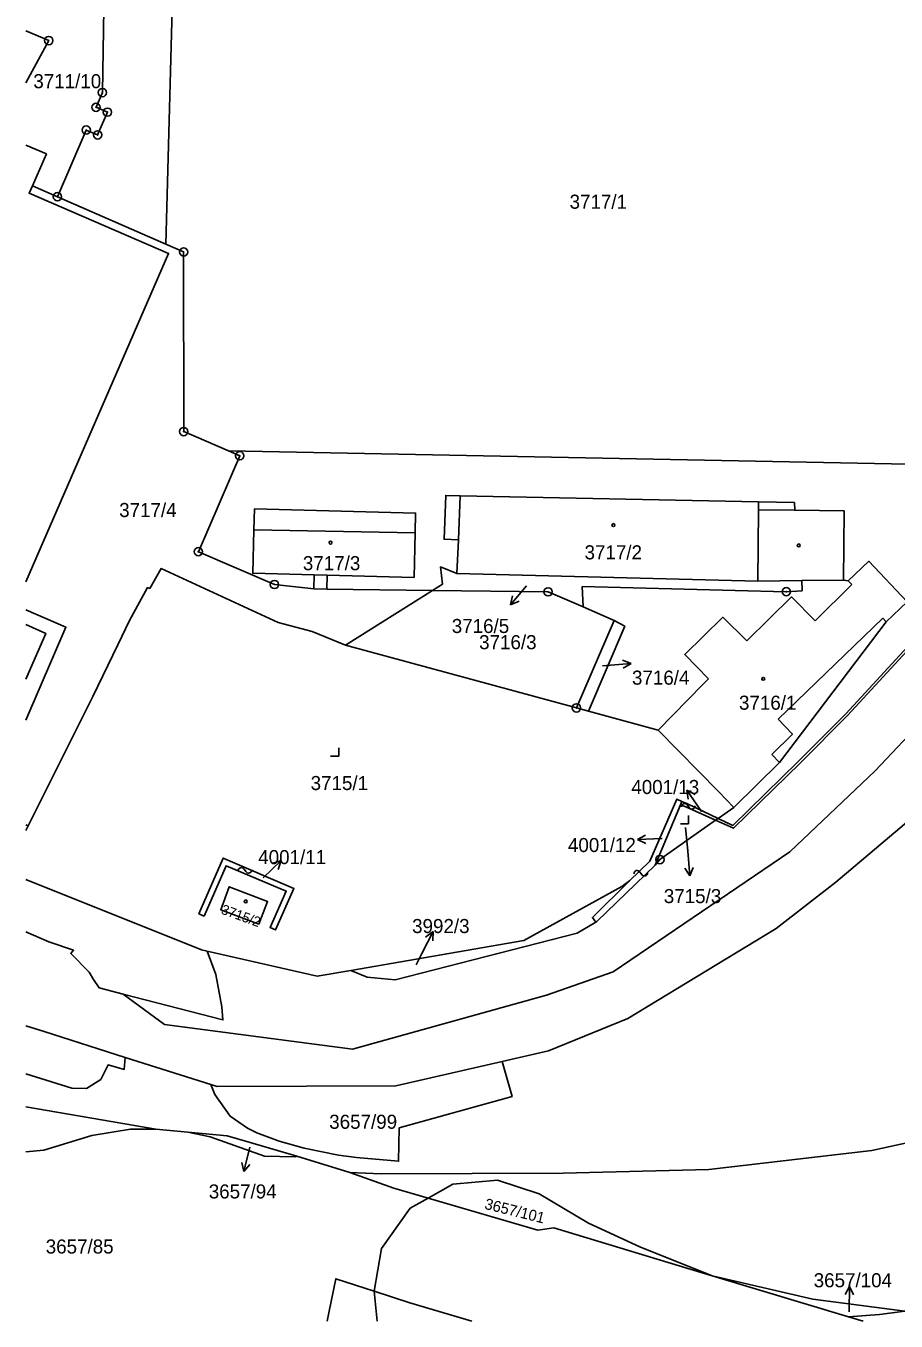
# Model space of a CAD drawing. Extents: x -747779 to -747197, y -965543 to -964919.
# Drawn here: x -747775.5 to -747670.2, y -965537.7 to -965381 of the extents above; entities that cross this region are included whole.
import ezdxf

# ---------------------------------------------------------------- set-up
doc = ezdxf.new("R2010")
doc.units = 0
for name, color, linetype in [('Hranice parcel', 7, 'Continuous'), ('Parcelní čísla', 7, 'Continuous'), ('Pop  PČ popisy', 7, 'Continuous'), ('Vnitřní kresba', 7, 'Continuous'), ('Značky bodu BP', 7, 'Continuous'), ('Značky budov', 7, 'Continuous'), ('Značky kultur', 7, 'Continuous')]:
    doc.layers.add(name, color=color, linetype=linetype)

msp = doc.modelspace()

# ---------------------------------------------------------------- linework, layer by layer
at = {"layer": 'Hranice parcel'}
for p, q in [((-747771.71, -965401.67), (-747774.74, -965400.35)), ((-747740.69, -965449.11), (-747739.11, -965449.15)), ((-747739.11, -965449.15), (-747726.31, -965449.3)), ((-747726.31, -965449.3), (-747736.84, -965455.93)), ((-747681.62, -965448.1), (-747676.6, -965448.05)), ((-747708.09, -965451.3), (-747704.33, -965452.92)), ((-747708.9, -965463.51), (-747704.33, -965452.92)), ((-747708.9, -965463.51), (-747736.84, -965455.93)), ((-747707.46, -965463.9), (-747708.9, -965463.51)), ((-747696.3, -965475.23), (-747699.39, -965482.54)), ((-747696.13, -965474.83), (-747696.3, -965475.23)), ((-747691.74, -965476.88), (-747689.84, -965475.54)), ((-747692.06, -965477.11), (-747691.74, -965476.88)), ((-747775.25, -965477.78), (-747775.53, -965477.67)), ((-747775.53, -965478.34), (-747775.25, -965477.78)), ((-747763.53, -965505.79), (-747753.16, -965509.09)), ((-747755.94, -965514.84), (-747759.81, -965514.49)), ((-747736.34, -965519.7), (-747742.72, -965517.76)), ((-747675.99, -965537.16), (-747692.46, -965532.2))]:
    msp.add_line(p, q, dxfattribs=at)
for points in [[(-747766.44, -965371.1), (-747765.97, -965371.3), (-747766.27, -965389.07), (-747767.04, -965390.85), (-747765.66, -965391.44), (-747766.85, -965394.19), (-747768.23, -965393.6), (-747771.71, -965401.67)], [(-747775.53, -965387.9), (-747772.76, -965382.78), (-747775.53, -965381.59)], [(-747774.74, -965400.35), (-747773.05, -965396.49), (-747775.53, -965395.44)], [(-747775.53, -965448.26), (-747758.26, -965408.52), (-747775.14, -965401.25), (-747774.74, -965400.35)], [(-747771.71, -965401.67), (-747758.58, -965407.41), (-747756.44, -965408.35), (-747756.43, -965430.08), (-747750.99, -965432.43), (-747749.65, -965433.01), (-747754.66, -965444.61), (-747745.45, -965448.58), (-747740.69, -965449.11)], [(-747629.27, -965410.12), (-747631.7, -965414.28), (-747634.55, -965418.49), (-747640.77, -965425.89), (-747653.68, -965440.12), (-747676.11, -965464.41), (-747681.84, -965470.18), (-747689.91, -965478.08), (-747692.06, -965477.11)], [(-747691.74, -965476.88), (-747689.97, -965477.72), (-747682.05, -965470.01), (-747676.31, -965464.21), (-747653.9, -965439.92), (-747641, -965425.7), (-747634.78, -965418.31), (-747631.96, -965414.13), (-747629.97, -965410.8)], [(-747736.34, -965519.7), (-747732.55, -965519.88), (-747710.49, -965519.81), (-747692.88, -965519.37), (-747673.14, -965517.04), (-747653.27, -965512.7), (-747638.07, -965508.19), (-747622.48, -965502.29), (-747614.4, -965496.49), (-747610.15, -965488.46), (-747607.5, -965480.29), (-747606.19, -965476.23), (-747605.56, -965473.4), (-747603.85, -965465.74), (-747603.43, -965453.35), (-747605.28, -965431.15), (-747605.34, -965430.88)], [(-747723.38, -965447.24), (-747723.19, -965443.16), (-747724.92, -965443.1), (-747724.71, -965437.8), (-747722.99, -965437.87), (-747686.87, -965438.58), (-747682.52, -965438.67), (-747682.49, -965439.59), (-747676.5, -965439.68), (-747676.6, -965448.05)], [(-747740.69, -965449.11), (-747740.65, -965447.41), (-747748.07, -965447.22), (-747747.93, -965441.98), (-747747.87, -965439.44), (-747728.36, -965439.94), (-747728.43, -965442.34), (-747728.56, -965447.72), (-747739.07, -965447.45), (-747739.11, -965449.15)], [(-747676.6, -965448.05), (-747676, -965448.13), (-747673.52, -965445.77), (-747668.87, -965450.69)], [(-747736.84, -965455.93), (-747740.89, -965454.28), (-747745, -965453.19), (-747759.15, -965446.63), (-747760.55, -965449.06), (-747760.8, -965448.95), (-747763, -965452.95), (-747764.41, -965455.89), (-747767.41, -965462.12), (-747775.25, -965477.78)], [(-747726.31, -965449.3), (-747725.12, -965448.55), (-747725.35, -965446.46), (-747723.38, -965447.24)], [(-747723.38, -965447.24), (-747686.93, -965448.16), (-747681.62, -965448.1)], [(-747708.09, -965451.3), (-747712.33, -965449.47), (-747726.31, -965449.3)], [(-747681.62, -965448.1), (-747681.6, -965449.33), (-747683.5, -965449.45), (-747708.19, -965448.83), (-747708.09, -965451.3)], [(-747689.84, -965475.54), (-747684.31, -965470.11), (-747671.42, -965453.1), (-747668.87, -965450.69)], [(-747775.53, -965464.99), (-747770.69, -965453.75), (-747775.53, -965451.65)], [(-747704.33, -965452.92), (-747703.06, -965453.64), (-747707.46, -965463.9)], [(-747689.84, -965475.54), (-747691.71, -965473.63), (-747699.01, -965466.2), (-747707.46, -965463.9)], [(-747717.91, -965506.29), (-747712.29, -965505), (-747702.68, -965501.08), (-747684.71, -965490.18), (-747677.49, -965484.61), (-747661.4, -965470.99)], [(-747702.46, -965484.44), (-747700.02, -965482.04), (-747696.77, -965474.55), (-747696.13, -965474.83)], [(-747692.06, -965477.11), (-747695.65, -965475.49), (-747696.3, -965475.23)], [(-747696.13, -965474.83), (-747695.47, -965475.12), (-747691.74, -965476.88)], [(-747692.06, -965477.11), (-747698.8, -965481.86), (-747699.39, -965482.54)], [(-747753.94, -965488.7), (-747754.58, -965488.42), (-747751.65, -965481.68), (-747743.09, -965485.37), (-747745.31, -965490.36), (-747745.97, -965490.09), (-747744.02, -965485.7), (-747751.31, -965482.6), (-747753.94, -965488.7)], [(-747699.39, -965482.54), (-747706.43, -965489.36), (-747706.57, -965489.44)], [(-747775.53, -965484.27), (-747754.29, -965492.79), (-747753.6, -965492.95)], [(-747747.34, -965489.69), (-747751.95, -965487.92), (-747750.91, -965485.14), (-747746.28, -965486.94), (-747747.34, -965489.69)], [(-747736.22, -965495.27), (-747715.26, -965491.64), (-747703.42, -965485.11), (-747702.46, -965484.44)], [(-747706.57, -965489.44), (-747706.96, -965488.85), (-747702.46, -965484.44)], [(-747706.57, -965489.44), (-747708.81, -965490.76), (-747730.82, -965496.39), (-747734.22, -965496.07), (-747736.22, -965495.27)], [(-747753.6, -965492.95), (-747752.56, -965495.77), (-747751.81, -965499.69), (-747751.69, -965501.26), (-747763.74, -965498.13), (-747766.68, -965497.39), (-747767.33, -965496.36), (-747767.88, -965495.49), (-747770.1, -965493.22), (-747769.96, -965493.06), (-747769.75, -965492.82), (-747772.74, -965491.8), (-747775.53, -965490.61)], [(-747753.6, -965492.95), (-747740.26, -965495.97), (-747736.22, -965495.27)], [(-747775.53, -965501.99), (-747773.32, -965502.67), (-747763.53, -965505.79)], [(-747763.53, -965505.79), (-747763.63, -965507.24), (-747765.58, -965506.7), (-747766.48, -965508.47), (-747768.2, -965509.56), (-747769.97, -965509.5), (-747775.53, -965507.8)], [(-747717.91, -965506.29), (-747716.68, -965510.51), (-747730.34, -965514.33), (-747730.43, -965518.35), (-747735.52, -965517.9), (-747737.71, -965517.6), (-747741.87, -965516.77), (-747744.87, -965515.92), (-747747.6, -965514.91), (-747748.7, -965514.34), (-747750.8, -965512.91), (-747752.67, -965510.28), (-747753.16, -965509.09)], [(-747753.16, -965509.09), (-747752.39, -965509.33), (-747730.76, -965509.24), (-747717.91, -965506.29)], [(-747759.81, -965514.49), (-747775.53, -965511.77)], [(-747759.81, -965514.49), (-747762.85, -965514.47), (-747767.53, -965515.25), (-747773.34, -965517), (-747775.53, -965517.21)], [(-747742.72, -965517.76), (-747742.99, -965517.83), (-747746.64, -965517.74), (-747753.23, -965515.39), (-747755.94, -965514.84)], [(-747742.72, -965517.76), (-747748.38, -965516.09), (-747751.16, -965515.27), (-747755.94, -965514.84)], [(-747726.85, -965522.81), (-747730.99, -965521.6), (-747736.34, -965519.7)], [(-747692.46, -965532.2), (-747701.23, -965528.7), (-747707.43, -965525.84), (-747713.41, -965522.3), (-747718.46, -965520.64), (-747723.88, -965521.12), (-747726.85, -965522.81)], [(-747733.38, -965534.09), (-747732.51, -965528.91), (-747729.03, -965524.04), (-747726.85, -965522.81)], [(-747692.46, -965532.2), (-747711.65, -965526.41), (-747713.57, -965526.68), (-747726.85, -965522.81)], [(-747692.46, -965532.2), (-747680.3, -965535.03), (-747669.17, -965536.51)], [(-747733.38, -965534.09), (-747738.04, -965532.58), (-747738.81, -965536.5), (-747739.05, -965537.69)], [(-747721.55, -965537.69), (-747729.06, -965535.49), (-747733.38, -965534.09)], [(-747733.01, -965537.69), (-747733.38, -965534.09)], [(-747675.99, -965537.16), (-747672.22, -965536.89), (-747669.17, -965536.51)], [(-747674.22, -965537.69), (-747675.99, -965537.16)]]:
    msp.add_lwpolyline(points, dxfattribs=at)
at = {"layer": 'Pop  PČ popisy'}
for p, q in [((-747714.95, -965448.75), (-747716.88, -965451.05)), ((-747716.88, -965451.05), (-747716.62, -965449.96)), ((-747716.88, -965451.05), (-747715.85, -965450.6)), ((-747705.76, -965458.43), (-747705.27, -965458.39)), ((-747705.27, -965458.39), (-747702.28, -965458.13)), ((-747702.28, -965458.13), (-747703.32, -965457.72)), ((-747702.28, -965458.13), (-747703.23, -965458.71)), ((-747693.85, -965475.94), (-747695.53, -965473.45)), ((-747695.53, -965473.45), (-747694.55, -965474)), ((-747695.53, -965473.45), (-747695.38, -965474.56)), ((-747693.75, -965476.1), (-747693.85, -965475.94)), ((-747701.52, -965479.44), (-747700.54, -965478.9)), ((-747695.7, -965477.99), (-747695.44, -965480.85)), ((-747698.52, -965479.33), (-747701.52, -965479.44)), ((-747701.52, -965479.44), (-747700.5, -965479.9)), ((-747746.8, -965484.08), (-747744.64, -965481.99)), ((-747744.64, -965481.99), (-747745.71, -965482.33)), ((-747744.64, -965481.99), (-747745.01, -965483.05)), ((-747695.44, -965480.85), (-747695.18, -965483.84)), ((-747695.18, -965483.84), (-747695.77, -965482.89)), ((-747695.18, -965483.84), (-747694.77, -965482.8)), ((-747727.62, -965493.24), (-747726.26, -965490.57)), ((-747726.26, -965490.57), (-747727.16, -965491.23)), ((-747726.26, -965490.57), (-747726.27, -965491.69)), ((-747728.31, -965494.59), (-747727.62, -965493.24)), ((-747748.44, -965516.67), (-747749.17, -965519.58)), ((-747748.43, -965516.65), (-747748.44, -965516.67)), ((-747749.17, -965519.58), (-747749.41, -965518.49)), ((-747749.17, -965519.58), (-747748.44, -965518.73)), ((-747675.86, -965533.5), (-747676.38, -965534.49)), ((-747675.91, -965536.5), (-747675.86, -965533.5)), ((-747675.86, -965533.5), (-747675.37, -965534.51)), ((-747675.91, -965536.56), (-747675.91, -965536.5))]:
    msp.add_line(p, q, dxfattribs=at)
at = {"layer": 'Vnitřní kresba'}
for p, q in [((-747757.51, -965366.75), (-747758.58, -965407.41)), ((-747750.99, -965432.43), (-747654.25, -965434.32)), ((-747723.19, -965443.16), (-747722.99, -965437.87)), ((-747686.87, -965439.54), (-747686.93, -965448.16)), ((-747686.87, -965438.58), (-747686.87, -965439.54)), ((-747686.87, -965439.54), (-747682.49, -965439.59)), ((-747747.93, -965441.98), (-747728.43, -965442.34)), ((-747740.65, -965447.41), (-747739.07, -965447.45)), ((-747675.57, -965448.57), (-747680.01, -965452.97)), ((-747676, -965448.13), (-747675.57, -965448.57)), ((-747652.17, -965449.3), (-747672.75, -965471.13)), ((-747684.48, -965464.89), (-747671.83, -965452.66)), ((-747671.42, -965453.1), (-747671.83, -965452.66)), ((-747693.62, -965460.68), (-747692.92, -965460)), ((-747699.01, -965466.2), (-747693.62, -965460.68)), ((-747685.26, -965469.15), (-747684.31, -965470.11)), ((-747672.75, -965471.13), (-747683.08, -965480.94)), ((-747683.08, -965480.94), (-747704.46, -965495.43)), ((-747712.53, -965498.28), (-747704.46, -965495.43)), ((-747763.74, -965498.13), (-747758.75, -965501.81)), ((-747736.01, -965504.81), (-747712.53, -965498.28)), ((-747758.75, -965501.81), (-747736.01, -965504.81))]:
    msp.add_line(p, q, dxfattribs=at)
for points in [[(-747688.28, -965455.41), (-747682.87, -965450.08), (-747680.01, -965452.97)], [(-747692.92, -965460), (-747695.79, -965457.05), (-747691.17, -965452.54), (-747688.28, -965455.41)], [(-747775.53, -965453.44), (-747773.12, -965454.49), (-747775.53, -965460.04)], [(-747685.26, -965469.15), (-747682.76, -965466.67), (-747684.48, -965464.89)]]:
    msp.add_lwpolyline(points, dxfattribs=at)
at = {"layer": 'Značky bodu BP'}
for centre, radius in [((-747772.76, -965382.78), 0.5), ((-747772.76, -965382.78), 0.0303), ((-747766.27, -965389.07), 0.5), ((-747766.27, -965389.07), 0.0303), ((-747767.04, -965390.85), 0.5), ((-747767.04, -965390.85), 0.0303), ((-747765.66, -965391.44), 0.5), ((-747765.66, -965391.44), 0.0303), ((-747768.23, -965393.6), 0.5), ((-747768.23, -965393.6), 0.0303), ((-747766.85, -965394.19), 0.5), ((-747766.85, -965394.19), 0.0303), ((-747771.71, -965401.67), 0.5), ((-747771.71, -965401.67), 0.0303), ((-747756.44, -965408.35), 0.5), ((-747756.44, -965408.35), 0.0303), ((-747756.43, -965430.08), 0.5), ((-747756.43, -965430.08), 0.0303), ((-747749.65, -965433.01), 0.5), ((-747749.65, -965433.01), 0.0303), ((-747754.66, -965444.61), 0.5), ((-747754.66, -965444.61), 0.0303), ((-747745.45, -965448.58), 0.5), ((-747745.45, -965448.58), 0.0303), ((-747712.33, -965449.47), 0.5), ((-747712.33, -965449.47), 0.0303), ((-747683.5, -965449.45), 0.5), ((-747683.5, -965449.45), 0.0303), ((-747708.9, -965463.51), 0.5), ((-747708.9, -965463.51), 0.0303), ((-747698.8, -965481.86), 0.5), ((-747698.8, -965481.86), 0.0303)]:
    msp.add_circle(centre, radius, dxfattribs=at)
at = {"layer": 'Značky budov'}
for p, q in [((-747695.47, -965475.28), (-747695.27, -965475.54)), ((-747749.12, -965483.03), (-747748.92, -965483.29)), ((-747701.22, -965483.38), (-747701.02, -965483.64))]:
    msp.add_line(p, q, dxfattribs=at)
for centre in [(-747704.43, -965441.39), (-747738.66, -965443.52), (-747682, -965443.85), (-747686.29, -965460), (-747748.92, -965486.92)]:
    msp.add_circle(centre, 0.175, dxfattribs=at)
for centre, start, end in [((-747695.81, -965475.47), 29.2914, 181.2189), ((-747694.93, -965475.35), 209.2914, 1.2189), ((-747749.46, -965483.22), 29.2914, 181.2189), ((-747748.58, -965483.1), 209.2914, 1.2189), ((-747701.56, -965483.57), 29.2914, 181.2189), ((-747700.68, -965483.45), 209.2914, 1.2189)]:
    msp.add_arc(centre, 0.394, start, end, dxfattribs=at)
at = {"layer": 'Značky kultur'}
for p, q in [((-747738.66, -965469.34), (-747737.66, -965469.34)), ((-747737.66, -965469.34), (-747737.66, -965468.34)), ((-747696.32, -965477.54), (-747695.32, -965477.54)), ((-747695.32, -965477.54), (-747695.32, -965476.54))]:
    msp.add_line(p, q, dxfattribs=at)

# ---------------------------------------------------------------- texts
at = {"layer": 'Parcelní čísla'}
for s, p in [('3711/10', (-747774.63, -965388.54)), ('3717/1', (-747709.73, -965403.12)), ('3717/4', (-747764.24, -965440.42)), ('3717/2', (-747707.92, -965445.54)), ('3717/3', (-747742.01, -965446.85)), ('3716/5', (-747723.99, -965454.45)), ('3716/3', (-747720.68, -965456.41)), ('3716/4', (-747702.18, -965460.7)), ('3716/1', (-747689.23, -965463.73)), ('3715/1', (-747741.07, -965473.45)), ('4001/13', (-747702.26, -965473.93)), ('4001/12', (-747709.93, -965480.95)), ('4001/11', (-747747.41, -965482.41)), ('3715/3', (-747698.33, -965487.13)), ('3992/3', (-747728.79, -965490.75)), ('3657/99', (-747738.82, -965514.43)), ('3657/94', (-747753.4, -965522.86)), ('3657/85', (-747773.13, -965529.52)), ('3657/104', (-747680.19, -965533.6))]:
    msp.add_text(s, height=1.7, dxfattribs=at).set_placement(p)
for s, height, rotation, p in [('3715/2', 1.2, 340, (-747752.01, -965488.37)), ('3657/101', 1.329, 346, (-747720.11, -965524.1))]:
    msp.add_text(s, height=height, rotation=rotation, dxfattribs=at).set_placement(p)

doc.saveas('drawing.dxf')
